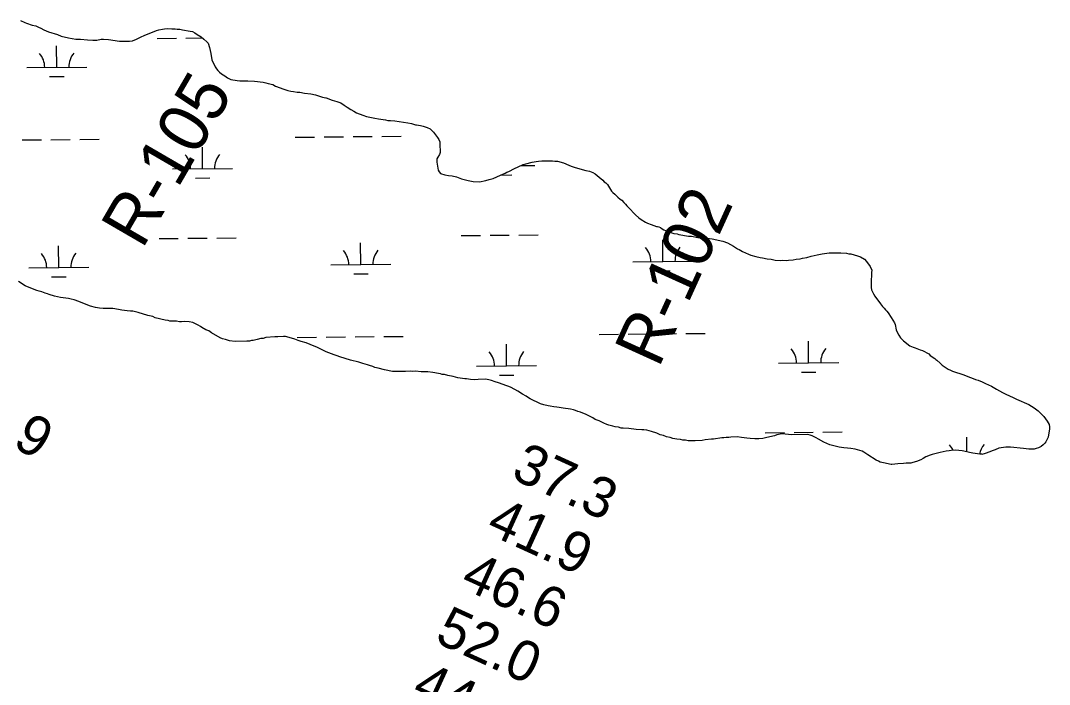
# Model space of a CAD drawing. Extents: x 3146026 to 3183936, y 897894 to 923344.
# Drawn here: x 3158441 to 3160150, y 913413 to 914516 of the extents above; entities that cross this region are included whole.
import ezdxf

# ---------------------------------------------------------------- set-up
doc = ezdxf.new("R2010")
doc.units = 0
for name, color, linetype in [('V-RIVR-RANG', 7, 'Continuous'), ('V-RIVR-RANG-IDEN', 7, 'Continuous'), ('V-WETL-SWMP', 7, 'Continuous')]:
    doc.layers.add(name, color=color, linetype=linetype)

msp = doc.modelspace()

# ---------------------------------------------------------------- linework, layer by layer
at = {"layer": 'V-WETL-SWMP'}
for p, q in [((3158500.9, 914438.7), (3158500.5, 914474.7)), ((3158667.5, 914486.8), (3158699.5, 914487.1)), ((3158715.5, 914487.3), (3158742.6, 914487.6)), ((3158450.9, 914438.2), (3158550.9, 914439.2)), ((3158489, 914423.2), (3158513, 914423.4)), ((3158443.2, 914318.1), (3158475.2, 914318.4)), ((3158491.2, 914318.5), (3158523.2, 914318.9)), ((3158539.2, 914319), (3158571.2, 914319.3)), ((3158897.1, 914322.6), (3158929.1, 914322.9)), ((3158945.1, 914323.1), (3158977.1, 914323.4)), ((3158993.1, 914323.6), (3159025.1, 914323.9)), ((3159041.1, 914324), (3159073.1, 914324.3)), ((3158743, 914270.3), (3158742.7, 914306.3)), ((3158693, 914269.8), (3158793, 914270.8)), ((3159272, 914275.6), (3159294.9, 914275.8)), ((3158731.2, 914254.8), (3158755.2, 914255)), ((3159237.9, 914259.8), (3159257.1, 914260)), ((3158670.8, 914154.2), (3158702.8, 914154.5)), ((3158718.8, 914154.6), (3158750.8, 914155)), ((3158766.8, 914155.1), (3158798.8, 914155.4)), ((3159172.7, 914159.2), (3159204.7, 914159.5)), ((3159220.7, 914159.6), (3159252.7, 914160)), ((3159268.7, 914160.1), (3159300.7, 914160.4)), ((3159508, 914116.1), (3159507.6, 914152.1)), ((3158504.2, 914106.1), (3158503.8, 914142.1)), ((3159006.1, 914111.1), (3159005.7, 914147.1)), ((3159458, 914115.6), (3159558, 914116.6)), ((3158454.2, 914105.6), (3158554.2, 914106.6)), ((3158956.1, 914110.6), (3159056.1, 914111.6)), ((3159496.1, 914100.5), (3159520.1, 914100.8)), ((3158492.3, 914090.5), (3158516.3, 914090.8)), ((3158994.2, 914095.5), (3159018.2, 914095.8)), ((3159402.3, 913994.9), (3159434.3, 913995.3)), ((3159450.3, 913995.4), (3159482.3, 913995.7)), ((3159498.3, 913995.9), (3159530.3, 913996.2)), ((3159546.3, 913996.4), (3159578.3, 913996.7)), ((3158900.4, 913989.9), (3158932.4, 913990.3)), ((3158948.4, 913990.4), (3158980.4, 913990.7)), ((3158996.4, 913990.9), (3159028.4, 913991.2)), ((3159044.4, 913991.4), (3159076.4, 913991.7)), ((3159248.2, 913942.7), (3159247.9, 913978.7)), ((3159750.1, 913947.7), (3159749.8, 913983.7)), ((3159198.2, 913942.2), (3159298.2, 913943.2)), ((3159700.1, 913947.2), (3159800.1, 913948.2)), ((3159236.4, 913927.1), (3159260.4, 913927.3)), ((3159738.3, 913932.1), (3159762.3, 913932.4)), ((3159677.9, 913831.5), (3159709.9, 913831.8)), ((3159725.9, 913832), (3159757.9, 913832.3)), ((3159773.9, 913832.5), (3159805.9, 913832.8)), ((3160013, 913799.9), (3160012.8, 913824.4))]:
    msp.add_line(p, q, dxfattribs=at)
for points in [[(3158440.5, 914516.4), (3158448, 914513.3), (3158450.4, 914512.1), (3158459.9, 914508.6), (3158466.3, 914507.4), (3158470.2, 914505.5), (3158474.2, 914503.9), (3158479.4, 914501.2), (3158486.9, 914497.7), (3158501.9, 914493), (3158508.3, 914490.3), (3158520.2, 914487.6), (3158532.4, 914485.7), (3158540.3, 914485.3), (3158551.8, 914484.2), (3158560.9, 914483.8), (3158567.6, 914483.9), (3158574.7, 914485.5), (3158578.3, 914485.5), (3158586.6, 914485.2), (3158604.8, 914482.1), (3158621.8, 914482.2), (3158626.6, 914483), (3158633.3, 914485.4), (3158640.8, 914489.4), (3158645.9, 914491.8), (3158666.4, 914499.9), (3158670.4, 914501.1), (3158676.3, 914501.9), (3158679.8, 914502.7), (3158685.4, 914503.5), (3158692.1, 914502.8), (3158697.6, 914502.4), (3158700.8, 914502), (3158705.5, 914502), (3158709.5, 914500.9), (3158722.6, 914499), (3158726.1, 914498.2), (3158730.1, 914496.3), (3158734.1, 914493.5), (3158740.8, 914489.2), (3158745.2, 914485.3), (3158749.9, 914481.3), (3158752.3, 914478.6), (3158754.7, 914471.9), (3158756.8, 914461.6), (3158758.4, 914450.9), (3158764, 914439.5), (3158766, 914436.3), (3158768.4, 914433.6), (3158771.2, 914430.8), (3158774.4, 914428.1), (3158779.9, 914424.6), (3158784.7, 914421), (3158789.8, 914418.7), (3158800.5, 914416.8), (3158804.9, 914416.4), (3158818.3, 914416.5), (3158829.4, 914415.7)], [(3158829.4, 914415.7), (3158843.6, 914413.8), (3158848, 914412.7), (3158852, 914411.9), (3158859.9, 914410), (3158864.2, 914407.6), (3158878.1, 914402.2), (3158884.8, 914400.2), (3158889.6, 914399.1), (3158894.3, 914398.7), (3158900.3, 914397.5), (3158904.6, 914397.2), (3158912.6, 914395.6), (3158923.2, 914394.9), (3158930.8, 914393), (3158942.6, 914389.1), (3158947.8, 914387.9), (3158948.6, 914387.9), (3158958.5, 914384.4), (3158966.4, 914382.1), (3158973.1, 914379.8), (3158978.3, 914375.8), (3158983.5, 914372.3), (3158989.4, 914368.4), (3158994.2, 914365.6), (3158998.9, 914363.3), (3159009.2, 914359), (3159015.2, 914357.1), (3159023.9, 914355.1), (3159029.4, 914354.4), (3159035.4, 914353.2), (3159047.2, 914351.3), (3159050.8, 914350.5), (3159055.2, 914350.6), (3159062.7, 914349.8), (3159084, 914346.4), (3159090, 914345.2), (3159097.1, 914343.3), (3159098.3, 914343.3), (3159105.4, 914342.1), (3159109.8, 914341), (3159116.5, 914338.6), (3159121.3, 914336.3), (3159126.8, 914330.8), (3159133.2, 914322.1), (3159135.6, 914318.6), (3159137.6, 914315), (3159137.2, 914311.5), (3159138.1, 914297.2), (3159136.9, 914294.1), (3159133.8, 914289.7), (3159132.6, 914286.5), (3159132.3, 914281.4), (3159134.7, 914268), (3159136.3, 914265.2), (3159138.7, 914262.5), (3159145.4, 914260.1), (3159151.8, 914259), (3159157.7, 914258.6), (3159165.2, 914256.7), (3159173.5, 914253.5), (3159179.9, 914251.6), (3159184.6, 914250.4), (3159192.9, 914248.9), (3159203.2, 914248.6), (3159213.5, 914250.6), (3159219.4, 914252.2), (3159225.7, 914254.2), (3159238, 914259.8), (3159245.9, 914263), (3159248.6, 914264.6), (3159252.2, 914265.9), (3159261.2, 914270.6), (3159267.5, 914273.5), (3159275.8, 914277.5), (3159280.2, 914278.3), (3159290.8, 914281.1), (3159297.2, 914282.3), (3159301.5, 914282.7), (3159306.6, 914283.2), (3159324.4, 914283.3), (3159328.4, 914282.9), (3159332.7, 914282.9), (3159343, 914280.2), (3159351.4, 914276.3), (3159355.7, 914274.7), (3159362.1, 914272), (3159379.9, 914267.4), (3159385.8, 914266.2), (3159391.8, 914263.9), (3159395.3, 914261.5), (3159402.1, 914256.4), (3159408, 914251.3), (3159410.4, 914248.5), (3159413.2, 914246.6), (3159416, 914243.8), (3159420.8, 914235.9), (3159422.8, 914233.2), (3159424.8, 914230.8), (3159428, 914227.7), (3159433.1, 914223)], [(3159433.1, 914223), (3159436.7, 914219.8), (3159439.5, 914217.9), (3159443.1, 914214.3), (3159445.8, 914211.6), (3159448.2, 914208.4), (3159451, 914205.7), (3159462.5, 914193.5), (3159468.1, 914188.8), (3159472.1, 914185.6), (3159478.8, 914181.3), (3159482.4, 914179.7), (3159488.3, 914177.4), (3159497.4, 914174.3), (3159499, 914174.3), (3159501.4, 914173.5), (3159504.2, 914172.4), (3159507, 914170.4), (3159509.7, 914168.8), (3159512.5, 914167.7), (3159518.5, 914165.7), (3159522.8, 914163.8), (3159526, 914162.6), (3159531.5, 914161.8), (3159534.7, 914160.7), (3159550.5, 914158.4), (3159555.7, 914158), (3159566, 914156.1), (3159569.1, 914155.7), (3159572.3, 914155.7), (3159581, 914155), (3159585.3, 914154.2), (3159590.1, 914153.8), (3159607.5, 914150), (3159615.4, 914147.3), (3159620.2, 914144.1), (3159625.4, 914141.4), (3159631.7, 914137.1), (3159634.5, 914135.9), (3159640.4, 914132.8), (3159650, 914128.1), (3159654.3, 914126.5), (3159662.2, 914124.2), (3159669.8, 914122.7), (3159673.7, 914122.3), (3159681.2, 914120.7), (3159687.6, 914120), (3159694.3, 914118.4), (3159702.6, 914117.7), (3159707.3, 914118.1), (3159712.9, 914117.8), (3159716.4, 914118.2), (3159724.3, 914118.6), (3159729.5, 914119.8), (3159735.8, 914120.7), (3159740.1, 914121.9), (3159747.3, 914122.7), (3159754.4, 914124.7), (3159764.2, 914127.1), (3159772.5, 914128.8), (3159784, 914130.4), (3159803.8, 914130.5), (3159813.3, 914129.8), (3159816.8, 914129), (3159820.4, 914128.6), (3159831.5, 914125.5), (3159836.2, 914124), (3159843, 914119.7), (3159846.2, 914116.1), (3159852.5, 914107.9), (3159855.3, 914101.5), (3159854.6, 914097.6), (3159854.6, 914094.4), (3159853.9, 914083.3), (3159853.9, 914073.1), (3159854.7, 914069.1), (3159857.9, 914062.4), (3159859.9, 914058.5), (3159869.5, 914045.5), (3159873.1, 914041.1), (3159875.5, 914038.8), (3159877.8, 914035.6), (3159880.2, 914033.7), (3159882.2, 914030.9), (3159887.4, 914023), (3159892.6, 914014), (3159893.8, 914011.2), (3159895.8, 914002.5), (3159897.8, 913997.4), (3159899.8, 913993.8), (3159903, 913989.1), (3159905, 913986.8), (3159907.8, 913984.4), (3159918.5, 913976.1), (3159923.7, 913973.8), (3159927.2, 913972.6), (3159935.6, 913969.1), (3159939.5, 913968), (3159949.8, 913962.5), (3159952.2, 913960.1), (3159959.8, 913955)], [(3158720.9, 914015.7), (3158713.4, 914016.5), (3158707.9, 914016.1), (3158704.7, 914016), (3158699.5, 914016.8), (3158688.9, 914017.1), (3158685.7, 914017.9), (3158680.9, 914018.7), (3158664.3, 914022.5), (3158660.4, 914024.5), (3158652.4, 914026.4), (3158636.2, 914031.5), (3158627.1, 914033.4), (3158623.5, 914033.4), (3158617.6, 914034.1), (3158613.6, 914034.9), (3158608.9, 914035.3), (3158603.3, 914036.4), (3158593.8, 914038), (3158578, 914037.9), (3158571.7, 914038.6), (3158565, 914039.8), (3158556.7, 914041.7), (3158552.7, 914043.3), (3158537.6, 914049.9), (3158529.7, 914052.6), (3158524.6, 914053.4), (3158520.6, 914054.6), (3158507.1, 914056.1), (3158496.8, 914058.4), (3158488.1, 914061.1), (3158485.4, 914062.3), (3158481.4, 914063.4), (3158475.8, 914065.8), (3158471.5, 914066.9), (3158467.9, 914068.1), (3158455.2, 914072.8), (3158448.5, 914075.5), (3158437, 914082.6)], [(3159025.8, 913941.5), (3159020.7, 913943.5), (3159017.1, 913944.2), (3159009.6, 913946.6), (3159002.8, 913948.9), (3158989, 913952.4), (3158971.1, 913957.8), (3158966.8, 913959.4), (3158961.6, 913960.9), (3158948.2, 913966), (3158939.4, 913970.3), (3158934.3, 913973), (3158921.6, 913978.1), (3158915.3, 913980.8), (3158906.9, 913983.2), (3158902.2, 913984.7), (3158896.6, 913987.1), (3158887.1, 913989.8), (3158880.8, 913991.3), (3158877.6, 913991.7), (3158868.1, 913990.9), (3158863, 913990.8), (3158848.4, 913989.6), (3158843.6, 913988.4), (3158840.1, 913987.9), (3158833.8, 913986.3), (3158827.4, 913985.1), (3158824.3, 913984.7), (3158821.1, 913983.9), (3158816.4, 913983.5), (3158797.4, 913983.3), (3158787.9, 913984.1), (3158781.2, 913986.4), (3158776.4, 913987.6), (3158772.1, 913989.5), (3158758.2, 913997.8), (3158753.4, 914000.9), (3158748.7, 914002.8), (3158741.9, 914006.4), (3158739.5, 914008.3), (3158736, 914010.3), (3158726.8, 914014.6), (3158720.9, 914015.7)], [(3159959.8, 913955), (3159961.3, 913953.5), (3159963.3, 913951.9), (3159968.5, 913947.2), (3159972.1, 913943.6), (3159982, 913937.4), (3159986, 913935.8), (3159989.1, 913933.8), (3160008.1, 913927.6), (3160014.9, 913924.9), (3160023.6, 913921.8), (3160027.2, 913920.2), (3160031.9, 913919), (3160038.7, 913915.9), (3160044.2, 913913.6), (3160054.1, 913908.9), (3160059.7, 913905.4), (3160062.5, 913903.8), (3160072.4, 913898.3), (3160077.9, 913895.6), (3160089.8, 913890.1), (3160095.4, 913887.4), (3160116, 913878.4), (3160124.7, 913872.9), (3160131.5, 913867.8), (3160141, 913858.8), (3160146.6, 913850.9), (3160149.8, 913845), (3160150.2, 913841.4), (3160150.2, 913838.2), (3160147.9, 913824), (3160144.4, 913816.5), (3160142.4, 913814.1), (3160139.7, 913811.3), (3160136.5, 913808.5), (3160131.8, 913806.5), (3160128.3, 913805.3), (3160125.1, 913804.5), (3160120.7, 913804.1), (3160116, 913804), (3160106.9, 913805.6), (3160085.5, 913807.4), (3160078, 913807.8), (3160066.2, 913806.1), (3160060.2, 913803.3), (3160055.1, 913801.3), (3160051.2, 913800.1), (3160043.7, 913796.9), (3160038.1, 913795.3), (3160038.1, 913795.7), (3160034.6, 913795.7), (3160023.1, 913797.6), (3160017.6, 913798.8), (3160013.2, 913799.9), (3160005.3, 913801.5), (3159994.2, 913802.6), (3159987.1, 913802.1), (3159983.5, 913801.7), (3159978.8, 913800.9), (3159968.9, 913798.5), (3159955.5, 913795.6), (3159951.9, 913794.4), (3159944.8, 913791.6), (3159940.5, 913788.8), (3159936.6, 913786.8), (3159929.1, 913783.6), (3159923.5, 913782), (3159920, 913781.2), (3159915.2, 913781.2), (3159912.1, 913780.8), (3159907.7, 913780.7), (3159898.6, 913779.9), (3159888.4, 913778.7), (3159887.2, 913778.7), (3159874.5, 913781.3), (3159869, 913782.9), (3159866.2, 913784.1), (3159862.2, 913786), (3159848.3, 913795), (3159842, 913799.4), (3159839.2, 913800.9), (3159827.7, 913804), (3159820.2, 913805.6), (3159814.7, 913805.9), (3159808.7, 913806.7), (3159800.8, 913807.4), (3159785.4, 913811.7), (3159780.2, 913813.6), (3159775.5, 913816), (3159766.7, 913820.7), (3159762.8, 913823), (3159756, 913826.6), (3159752.5, 913827.7), (3159748.9, 913828.5), (3159722.4, 913828.3), (3159716.9, 913828.7), (3159705.8, 913829.8), (3159697.5, 913828.2), (3159693.2, 913826.6), (3159680.9, 913823.4), (3159673.8, 913822.1)], [(3159673.8, 913822.1), (3159667.5, 913821.3), (3159660.8, 913821.3), (3159653.2, 913822), (3159647.7, 913822.4), (3159638.6, 913823.9), (3159631.5, 913824.7), (3159620.8, 913824.2), (3159617.6, 913823.8), (3159612.9, 913823.8), (3159609.3, 913823), (3159605.8, 913823), (3159592.3, 913820.9), (3159588.8, 913820.9), (3159578.1, 913819.6), (3159573, 913818.8), (3159561.5, 913818), (3159555.6, 913817.9), (3159549.7, 913818.3), (3159545.7, 913819.1), (3159541.3, 913819.4), (3159537, 913820.2), (3159531.1, 913821), (3159524.7, 913822.1), (3159520, 913823.7), (3159514, 913824.8), (3159508.9, 913826.8), (3159503.7, 913828.3), (3159497.8, 913830.7), (3159489.1, 913833.8), (3159481.5, 913835.7), (3159476.4, 913836.5), (3159472.8, 913836.4), (3159463.7, 913837.2), (3159451.1, 913838.7), (3159442, 913839.4), (3159438.4, 913839.4), (3159434.1, 913840.6), (3159428.9, 913841.3), (3159425, 913842.5), (3159418.2, 913844.1), (3159414.7, 913845.2), (3159409.9, 913847.2), (3159402, 913851.1), (3159395.6, 913853.8), (3159391.3, 913856.2), (3159380.2, 913861.6), (3159371, 913865.5), (3159366.7, 913866.7), (3159362.7, 913868.3), (3159359.2, 913869.4), (3159354.4, 913870.6), (3159342.1, 913872.5), (3159335.8, 913873.6), (3159331.9, 913874), (3159326.7, 913874.8), (3159320.8, 913875.9), (3159317.2, 913876.3), (3159310.1, 913877.9), (3159304.5, 913879.8), (3159287.5, 913888), (3159284.7, 913889.6), (3159280.7, 913892.3), (3159274.8, 913895.8), (3159267.2, 913900.9), (3159256.1, 913906.8), (3159252.2, 913908.4), (3159248.6, 913909.5), (3159234.7, 913914.6), (3159229.2, 913916.2), (3159223.3, 913918.1), (3159218.5, 913919.3), (3159213.4, 913920.4), (3159201.1, 913920.3), (3159194.4, 913919.5), (3159188.4, 913919.9), (3159181.7, 913921), (3159178.6, 913921), (3159167.5, 913922.9), (3159159.6, 913924.9), (3159150.4, 913926.8), (3159145.3, 913928.3), (3159141.3, 913928.3), (3159138.6, 913929.5), (3159135, 913929.9), (3159125.9, 913931.4), (3159117.2, 913932.5), (3159113.2, 913932.5), (3159109.7, 913932.9), (3159106.5, 913932.9), (3159097, 913933.6), (3159091.5, 913933.2), (3159087.9, 913933.6), (3159080.4, 913933.1), (3159070.9, 913933.1), (3159063, 913933.4), (3159058.7, 913933.4), (3159045.6, 913936.1), (3159034.9, 913938.8), (3159029.4, 913940), (3159025.8, 913941.5)]]:
    msp.add_lwpolyline(points, dxfattribs=at)
for centre, start, end in [((3158445.6, 914438.6), 359.7992, 41.3429), ((3158556.1, 914439.7), 139.7992, 181.3429), ((3158687.8, 914270.2), 359.7992, 41.3429), ((3158798.3, 914271.3), 139.7992, 181.3429), ((3158950.8, 914111), 359.7992, 41.3429), ((3159061.3, 914112.1), 139.7992, 181.3429), ((3159452.7, 914116), 359.7992, 41.3429), ((3159563.2, 914117.1), 139.7992, 181.3429), ((3158448.9, 914106), 359.7992, 41.3429), ((3158559.4, 914107.1), 139.7992, 181.3429), ((3159193, 913942.6), 359.7992, 41.3429), ((3159303.5, 913943.7), 139.7992, 181.3429), ((3159694.9, 913947.6), 359.7992, 41.3429), ((3159805.4, 913948.7), 139.7992, 181.3429), ((3159957.9, 913788.3), 23.4026, 41.3429), ((3160068.4, 913789.4), 139.7992, 169.5537)]:
    msp.add_arc(centre, 35.2, start, end, dxfattribs=at)

# ---------------------------------------------------------------- texts
at = {"layer": 'V-RIVR-RANG'}
for s, rotation, p in [('32.9', 329.6983, (3158317.6, 913873)), ('37.3', 335.4383, (3159253.4, 913756.8)), ('41.9', 335.4383, (3159211.8, 913665.8)), ('46.6', 335.4383, (3159169, 913575.4)), ('52.0', 335.4383, (3159126.7, 913484.8)), ('44.8', 335.4383, (3159088, 913392.5))]:
    msp.add_text(s, height=67, rotation=rotation, dxfattribs=at).set_placement(p)
at = {"layer": 'V-RIVR-RANG-IDEN'}
for s, rotation, p in [('R-105', 59.8427, (3158642.8, 914135.1)), ('R-102', 65.5817, (3159500.8, 913937.6))]:
    msp.add_text(s, height=83, rotation=rotation, dxfattribs=at).set_placement(p)

doc.saveas('drawing.dxf')
